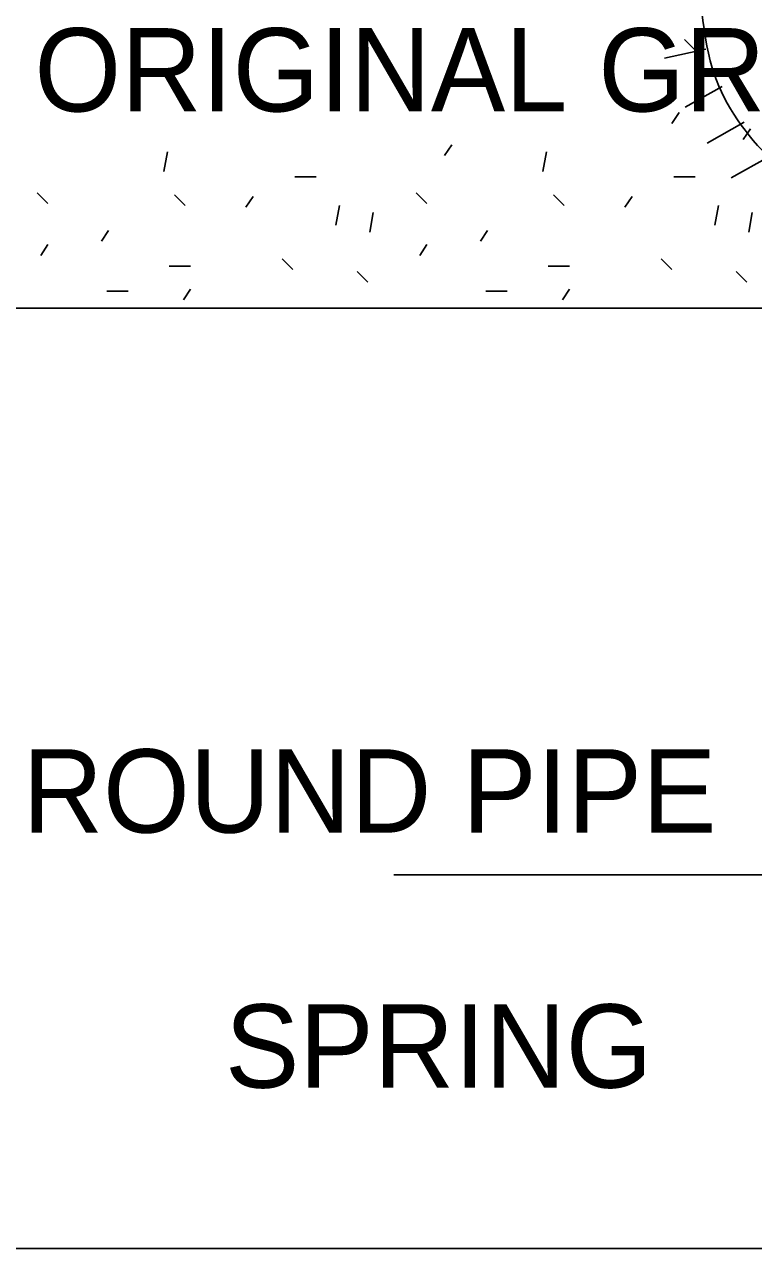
# Model space of a CAD drawing. Extents: x 1.32 to 7.47, y -3.56 to 5.14.
# Drawn here: x 2.979 to 3.503, y 3.447 to 4.328 of the extents above; entities that cross this region are included whole.
import ezdxf

# ---------------------------------------------------------------- set-up
doc = ezdxf.new("R2010")
doc.units = 0
for name, color, linetype in [('DETL-DIMS', 7, 'Continuous'), ('DETL-LINE', 7, 'Continuous'), ('DETL-NOTE', 7, 'Continuous'), ('DETL-PATT', 7, 'Continuous')]:
    doc.layers.add(name, color=color, linetype=linetype)

msp = doc.modelspace()

# ---------------------------------------------------------------- linework, layer by layer
at = {"layer": 'DETL-DIMS'}
msp.add_line((3.24452, 3.7159), (3.60333, 3.7159), dxfattribs=at)
at = {"layer": 'DETL-LINE'}
for p, q in [((2.59457, 4.12363), (5.01881, 4.12363)), ((2.59457, 3.44686), (5.01881, 3.44686))]:
    msp.add_line(p, q, dxfattribs=at)
msp.add_spline([(2.59457, 4.5663), (2.63955, 4.55129), (2.84713, 4.53562), (2.97246, 4.54737), (3.07821, 4.53954), (3.13696, 4.52778), (3.29754, 4.52386), (3.30929, 4.52386), (3.36021, 4.52386), (3.38245, 4.49737), (3.45812, 4.38279), (3.47379, 4.29657), (3.51295, 4.23387), (3.55212, 4.18685), (3.55995, 4.14766), (3.63437, 4.07712), (3.6657, 4.0105), (3.68137, 3.96739), (3.72445, 3.89294), (3.74403, 3.84983), (3.76362, 3.81064), (3.77928, 3.74402), (3.80278, 3.72051), (3.83803, 3.73619), (3.86936, 3.77537), (3.89286, 3.83024), (4.02603, 3.97131), (4.13202, 4.04566)], degree=3, dxfattribs=at)
at = {"layer": 'DETL-PATT'}
for p, q in [((3.45372, 4.3171), (3.46143, 4.30939)), ((3.46903, 4.31022), (3.43938, 4.30357)), ((3.48083, 4.28336), (3.45422, 4.26837)), ((3.44472, 4.25673), (3.44986, 4.26445)), ((3.4967, 4.25752), (3.47015, 4.24257)), ((3.4961, 4.24518), (3.50124, 4.25289)), ((3.28117, 4.23362), (3.2863, 4.24134)), ((3.08164, 4.23619), (3.07908, 4.22206)), ((3.35437, 4.23619), (3.3518, 4.22206)), ((3.51397, 4.23246), (3.48735, 4.21748)), ((3.17329, 4.21821), (3.1887, 4.21821)), ((3.44602, 4.21821), (3.46143, 4.21821)), ((2.98789, 4.20664), (2.9956, 4.19894)), ((3.08678, 4.20536), (3.09449, 4.19766)), ((3.13816, 4.19637), (3.14329, 4.20409)), ((3.26062, 4.20664), (3.26833, 4.19894)), ((3.35951, 4.20536), (3.36721, 4.19766)), ((3.41088, 4.19637), (3.41602, 4.20409)), ((3.20539, 4.19766), (3.20283, 4.18353)), ((3.47812, 4.19766), (3.47555, 4.18353)), ((3.22979, 4.19252), (3.22722, 4.17839)), ((3.50252, 4.19252), (3.49995, 4.17839)), ((3.03412, 4.17197), (3.03926, 4.17969)), ((3.30685, 4.17197), (3.31199, 4.17969)), ((2.99046, 4.1617), (2.9956, 4.16942)), ((3.26319, 4.1617), (3.26833, 4.16942)), ((3.16429, 4.15913), (3.172, 4.15143)), ((3.43702, 4.15913), (3.44472, 4.15143)), ((3.08293, 4.154), (3.09834, 4.154)), ((3.21824, 4.15014), (3.22594, 4.14244)), ((3.35566, 4.154), (3.37107, 4.154)), ((3.49096, 4.15014), (3.49867, 4.14244)), ((3.03797, 4.13602), (3.05338, 4.13602)), ((3.0932, 4.12959), (3.09834, 4.1373)), ((3.3107, 4.13602), (3.32611, 4.13602)), ((3.36593, 4.12959), (3.37107, 4.1373))]:
    msp.add_line(p, q, dxfattribs=at)

# ---------------------------------------------------------------- texts
at = {"layer": 'DETL-NOTE'}
for s, p in [('ORIGINAL GROUND', (2.98596, 4.26527)), ('UNDERGROUND PIPE', (2.62973, 3.74621)), ('SPRING', (3.12308, 3.56261))]:
    msp.add_text(s, height=0.06, dxfattribs=at).set_placement(p)

doc.saveas('drawing.dxf')
